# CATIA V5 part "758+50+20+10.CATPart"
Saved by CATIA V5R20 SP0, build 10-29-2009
Part number: 758+50+20+10
Revision: TUTTO
Definition: NON CONOSCIUTO
Nomenclature: 758+50+20+10
Source: Unknown
Bounding box of the stored display mesh (mm): x -24.818 to 24.818, y 0 to 20, z -25 to 25
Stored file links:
  C:\Users\Utente\Desktop\IO LAVORO\3D X SITO CF\X 3D SITO CF 27-09-2020\758\758+50+20+10.CATPart
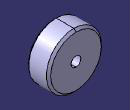
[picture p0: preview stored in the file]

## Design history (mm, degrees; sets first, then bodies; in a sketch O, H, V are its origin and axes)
Body1 "Importato1" (main body)
  Solid1: solid without history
